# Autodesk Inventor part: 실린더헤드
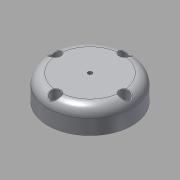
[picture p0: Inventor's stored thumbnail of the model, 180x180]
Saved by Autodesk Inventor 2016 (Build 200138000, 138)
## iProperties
Created: 2016-11
Part Number: 실린더헤드
Material: 알루미늄 6061
Document SubType Name: Modeling
Designer: mduedu
Density: 2.71 g/cm^3
Mass: 284.819 g
Surface Area: 227.25 cm^2
Volume: 105.099 cm^3
Appearance: 알루미늄 - 평지
Author: mduedu
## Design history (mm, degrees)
sketch "스케치1"
  geometry: C1 r 42.5 at (0, 0); 1 further point
  constraints: 1 centre point, 1 coincident
  dimensions: "d0" = 85 diameter of C1
extrude "돌출1" new body sketch "스케치1" distance "d1" = 25; taper "d2" = 0 deg
fillet "모깎기1" dims "d3" = 10
sketch "스케치2"
  geometry: C1 r 30 at (0, 0); 1 further point
  constraints: 1 centre point, 1 coincident
  dimensions: "d4" = 60 diameter of C1
extrude "돌출2" join sketch "스케치2" distance "d5" = 5; taper "d6" = 0 deg
sketch "스케치3"
  geometry: C1 r 25 at (0, 0); 1 further point
  constraints: 1 centre point, 1 coincident
  dimensions: "d7" = 50 diameter of C1
extrude "돌출3" cut sketch "스케치3" distance "d8" = 20; taper "d9" = 0 deg
hole "구멍1" diameter "d12" = 4.134; stored, may be unused: countersink angle "d16" = 90 deg, drill point angle "d18" = 118 deg; dims "d10" = 10, "d11" = 10, "d13" = 6, "d14" = 4, "d15" = 2, "d17" = 8
chamfer "모따기1" distance "d19" = 1; stored, may be unused: second distance "d20" = 2, angle "d21" = 45 deg
fillet "모깎기2" dims "d22" = 3
sketch "스케치4"
  geometry: C1 r 17.5 at (0, 0); 1 further point
  constraints: 1 centre point, 1 coincident
  dimensions: "d23" = 35 diameter of C1
extrude "돌출4" cut sketch "스케치4" distance "d24" = 2; taper "d25" = 0 deg
fillet "모깎기3" dims "d26" = 0.5
sketch "스케치5" dims "d32" = 70
  geometry: C1 r 5 at (0, 35); 3 further points
  constraints: 2 coincident, 2 vertical alignment, 1 centre point, 2 other
  dimensions: "d33" = 10 diameter of C1
extrude "돌출5" cut sketch "스케치5" distance "d34" = 10; taper "d35" = 0 deg
sketch "스케치6" dims "d39" = 70
  geometry: 6 further points
  constraints: 2 vertical alignment, 1 coincident, 7 other
  dimensions: "d42" = 360 deg dimension on point (0, -35) point (0, 0) (derived)
sketch "스케치7"
  geometry: 4 further points
  constraints: 4 other
hole "구멍2" sketch "스케치7" at (0, 70), (-35, 35), (35, 35), (0, 0) diameter "d44" = 5.5; stored, may be unused: countersink angle "d48" = 90 deg, drill point angle "d50" = 0 deg; dims "d45" = 6, "d46" = 4, "d47" = 2, "d49" = 8
fillet "모깎기4" dims "d51" = 0.5
node "솔리드1"
pattern_circular "원형 패턴1" dims angle "d37" = 360 deg
